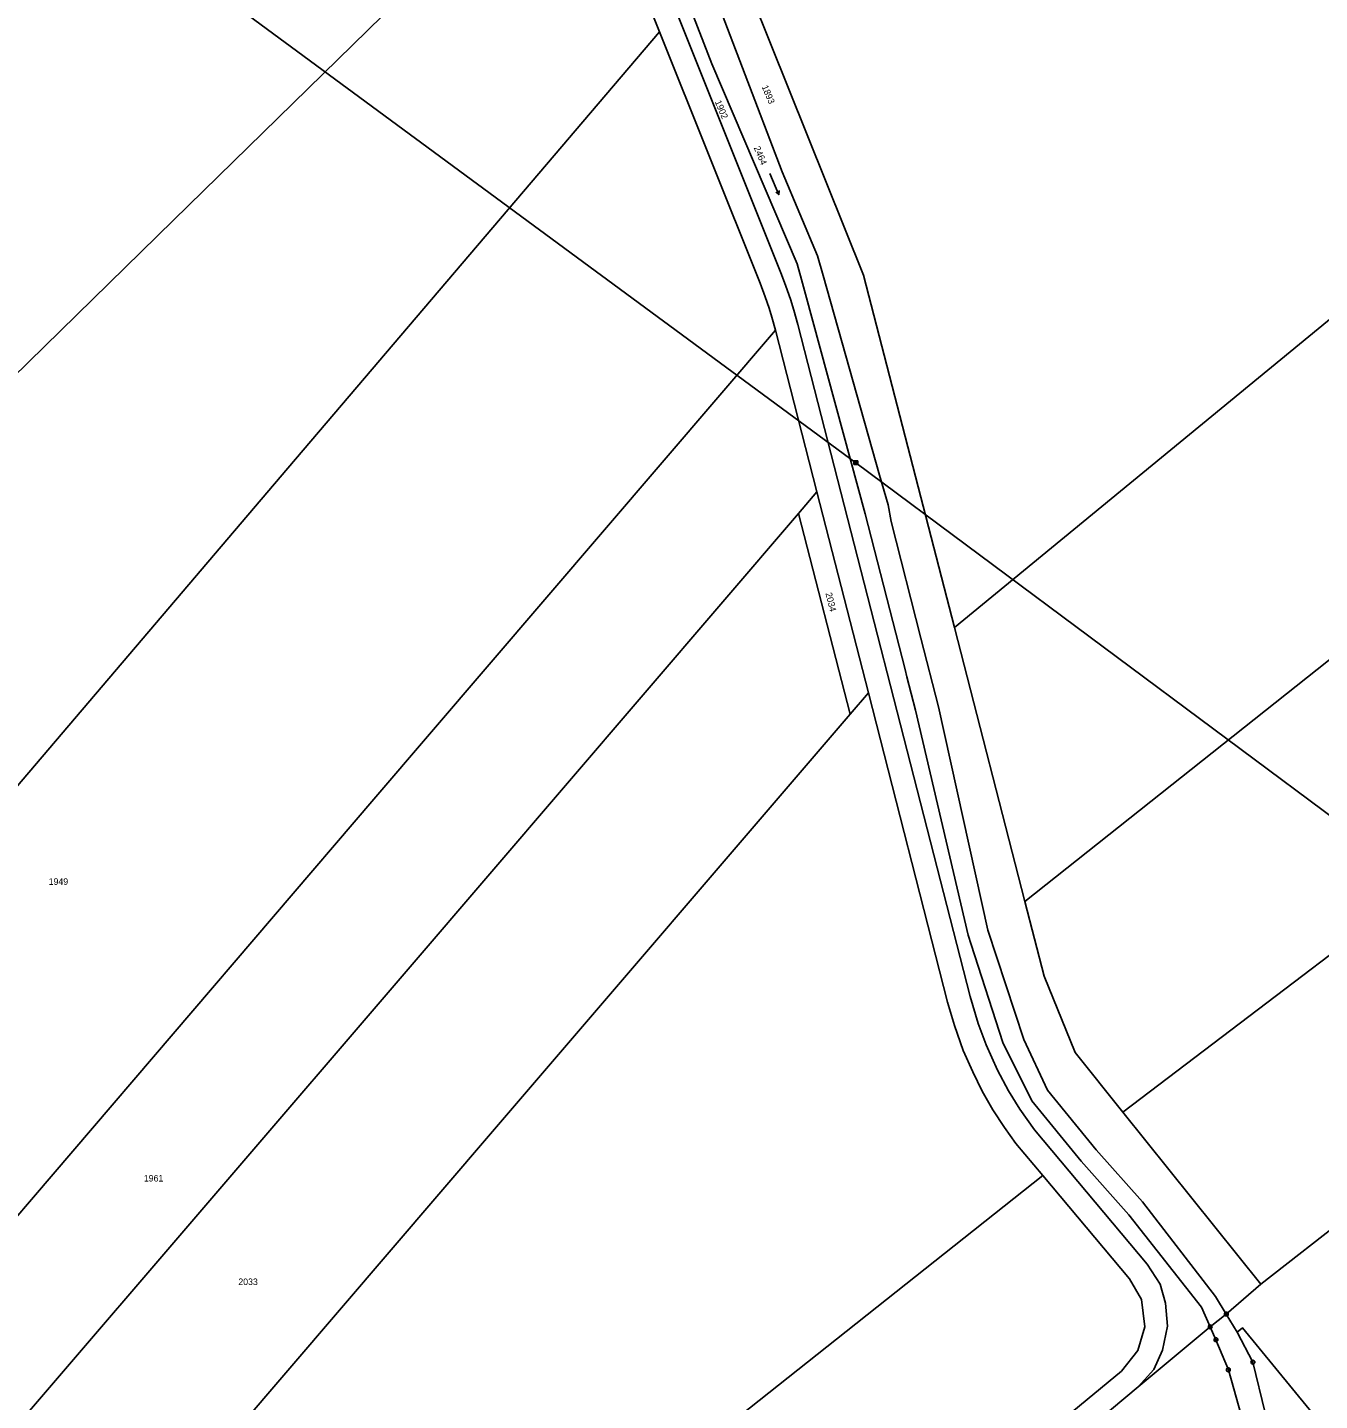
# Model space of a CAD drawing. Extents: x -504988 to -494607, y -1123820 to -1114018.
# Drawn here: x -501568.7 to -501232.9, y -1120604.7 to -1120247.9 of the extents above; entities that cross this region are included whole.
import ezdxf

# ---------------------------------------------------------------- set-up
doc = ezdxf.new("R2010")
doc.units = 0
for name, color, linetype in [('Hranice parcel', 7, 'Continuous'), ('Parcelní čísla', 7, 'Continuous'), ('Poz předměty', 7, 'Continuous'), ('Značky bodu BP', 7, 'Continuous'), ('Značky kultur', 7, 'Continuous')]:
    doc.layers.add(name, color=color, linetype=linetype)

msp = doc.modelspace()

# ---------------------------------------------------------------- linework, layer by layer
at = {"layer": 'Hranice parcel'}
for p, q in [((-501404.45, -1120249.05), (-501425.9, -1120195.48)), ((-501363.52, -1120368.63), (-501374.29, -1120326.57)), ((-501368.29, -1120374.19), (-501363.52, -1120368.63)), ((-501350.15, -1120420.8), (-501363.52, -1120368.63)), ((-501354.92, -1120426.36), (-501368.29, -1120374.19)), ((-501309.46, -1120475.02), (-501327.8, -1120403.85)), ((-501350.15, -1120420.8), (-501354.92, -1120426.36)), ((-501186.29, -1120526.21), (-501248.19, -1120574.48)), ((-501248.19, -1120574.48), (-501283.99, -1120529.75)), ((-501248.19, -1120574.48), (-501257.14, -1120582.25)), ((-501261.34, -1120585.56), (-501257.14, -1120582.25)), ((-501257.14, -1120582.25), (-501254.29, -1120586.94)), ((-501261.34, -1120585.56), (-501280.06, -1120601.16)), ((-501280.06, -1120601.16), (-501364.05, -1120671.17))]:
    msp.add_line(p, q, dxfattribs=at)
for points in [[(-501327.8, -1120403.85), (-501351.4, -1120312.32), (-501404.66, -1120179.5)], [(-501261.34, -1120585.56), (-501263.62, -1120580.47), (-501282.51, -1120556.48), (-501294.84, -1120542.51), (-501307.66, -1120526.86), (-501315.22, -1120511.72), (-501323.4, -1120486.24), (-501324.18, -1120483.81), (-501337.91, -1120425.3), (-501340.13, -1120416.63), (-501340.62, -1120414.73), (-501350.97, -1120374.34), (-501366.51, -1120317.27), (-501367.55, -1120313.46), (-501368.67, -1120309.33), (-501390.83, -1120257.4), (-501417.17, -1120189.27)], [(-501740.45, -1120503.19), (-501635.6, -1120400.62), (-501530.75, -1120298.05), (-501425.9, -1120195.48)], [(-501327.8, -1120403.85), (-501217.73, -1120313.47), (-501107.66, -1120223.08)], [(-501404.12, -1120233.67), (-501372.72, -1120312.15), (-501371.56, -1120315.17), (-501370.4, -1120318.55), (-501369.5, -1120321.42), (-501368.48, -1120325.08), (-501323.74, -1120499.74), (-501321.65, -1120506.76), (-501319.53, -1120512.26), (-501316.61, -1120518.89), (-501313.71, -1120524.28), (-501310.77, -1120529.03), (-501306.99, -1120534.38), (-501277.67, -1120569.26), (-501274.35, -1120574.51), (-501272.91, -1120579.44), (-501272.42, -1120585.43), (-501273.68, -1120591.65), (-501276.01, -1120596.62), (-501280.06, -1120601.16)], [(-501393.18, -1120231.31), (-501372.59, -1120285.43), (-501363.37, -1120307.31), (-501361.94, -1120312.37), (-501347.23, -1120364.25), (-501345.04, -1120371.97), (-501344.25, -1120376.28), (-501336.5, -1120406.6), (-501331.95, -1120424.43), (-501319.09, -1120482.5), (-501309.78, -1120510.94), (-501303.61, -1120524.09), (-501290.93, -1120539.58), (-501278.88, -1120553.13), (-501259.92, -1120577.69), (-501257.14, -1120582.25)], [(-501694.2, -1120589.18), (-501597.62, -1120475.8), (-501501.03, -1120362.43), (-501404.45, -1120249.05)], [(-501374.29, -1120326.57), (-501375.21, -1120323.23), (-501375.93, -1120320.89), (-501376.94, -1120317.94), (-501378.29, -1120314.39), (-501404.45, -1120249.05)], [(-501309.46, -1120475.02), (-501181.95, -1120373.83), (-501054.44, -1120272.63)], [(-501583.01, -1120570.44), (-501478.65, -1120448.5), (-501374.29, -1120326.57)], [(-501671.16, -1120727.67), (-501570.2, -1120609.84), (-501469.25, -1120492.02), (-501368.29, -1120374.19)], [(-501283.99, -1120529.75), (-501183.6, -1120453.57), (-501083.21, -1120377.38)], [(-501304.82, -1120546.26), (-501311.85, -1120537.89), (-501314.81, -1120533.74), (-501317.8, -1120529.14), (-501320.57, -1120524.3), (-501323.05, -1120519.35), (-501325.48, -1120513.73), (-501327.77, -1120507.26), (-501329.55, -1120501.23), (-501350.15, -1120420.8)], [(-501354.92, -1120426.36), (-501447.86, -1120534.83), (-501540.79, -1120643.3), (-501633.73, -1120751.77)], [(-501283.99, -1120529.75), (-501296.38, -1120514.27), (-501304.46, -1120494.41), (-501309.46, -1120475.02)], [(-501560.18, -1120786.67), (-501527.75, -1120804.11), (-501524.45, -1120805.17), (-501521.73, -1120805.12), (-501519.08, -1120804.28), (-501516.34, -1120802.26), (-501462.32, -1120744.93), (-501457.75, -1120740.38), (-501452.9, -1120736.12), (-501368.66, -1120666.62), (-501284.41, -1120597.12), (-501280.12, -1120591.76), (-501278.34, -1120585.57), (-501279.22, -1120578.46), (-501282.26, -1120573.12), (-501304.82, -1120546.26)], [(-501304.82, -1120546.26), (-501429.67, -1120645.23), (-501530.63, -1120737.12), (-501555.87, -1120775.45)], [(-501246.29, -1120653.02), (-501250.02, -1120623.58), (-501253.23, -1120608.78), (-501256.61, -1120596.72), (-501259.83, -1120588.92), (-501261.34, -1120585.56)], [(-501195.89, -1120655.5), (-501252.94, -1120585.81), (-501254.29, -1120586.94)], [(-501254.29, -1120586.94), (-501250.23, -1120594.76), (-501247.04, -1120607.91), (-501244.45, -1120622.7), (-501241.9, -1120650.35), (-501238.49, -1120682.81)]]:
    msp.add_lwpolyline(points, dxfattribs=at)
at = {"layer": 'Poz předměty'}
for p, q in [((-501521.61, -1120237.13), (-501353.43, -1120361.04)), ((-501353.93, -1120360.54), (-501352.93, -1120360.54)), ((-501353.93, -1120361.54), (-501353.93, -1120360.54)), ((-501353.93, -1120360.74), (-501352.93, -1120360.74)), ((-501353.93, -1120360.94), (-501352.93, -1120360.94)), ((-501353.93, -1120361.14), (-501352.93, -1120361.14)), ((-501353.93, -1120361.34), (-501352.93, -1120361.34)), ((-501353.93, -1120361.54), (-501352.93, -1120361.54)), ((-501353.73, -1120361.54), (-501353.73, -1120360.54)), ((-501353.53, -1120361.54), (-501353.53, -1120360.54)), ((-501353.43, -1120361.04), (-501198.35, -1120476.45)), ((-501353.33, -1120361.54), (-501353.33, -1120360.54)), ((-501353.13, -1120361.54), (-501353.13, -1120360.54)), ((-501352.93, -1120361.54), (-501352.93, -1120360.54))]:
    msp.add_line(p, q, dxfattribs=at)
at = {"layer": 'Značky bodu BP'}
for centre, radius in [((-501257.14, -1120582.25), 0.5), ((-501257.14, -1120582.25), 0.0303), ((-501261.34, -1120585.56), 0.5), ((-501261.34, -1120585.56), 0.0303), ((-501259.83, -1120588.92), 0.5), ((-501259.83, -1120588.92), 0.0303), ((-501256.61, -1120596.72), 0.5), ((-501256.61, -1120596.72), 0.0303), ((-501250.23, -1120594.76), 0.5), ((-501250.23, -1120594.76), 0.0303)]:
    msp.add_circle(centre, radius, dxfattribs=at)
at = {"layer": 'Značky kultur'}
for p, q in [((-501375.74, -1120285.89), (-501373.4, -1120291.41)), ((-501373.4, -1120291.41), (-501374.24, -1120290.71)), ((-501373.4, -1120291.41), (-501373.32, -1120290.31))]:
    msp.add_line(p, q, dxfattribs=at)

# ---------------------------------------------------------------- texts
at = {"layer": 'Parcelní čísla'}
for s, rotation, p in [('1893', 293, (-501377.91, -1120263.34)), ('1902', 293, (-501390.09, -1120267.25)), ('2464', 293, (-501379.97, -1120279.19)), ('2034', 284, (-501361.31, -1120394.97))]:
    msp.add_text(s, height=1.7, rotation=rotation, dxfattribs=at).set_placement(p)
for s, p in [('1949', (-501563.15, -1120470.72)), ('1961', (-501538.42, -1120547.81)), ('2033', (-501513.87, -1120574.71))]:
    msp.add_text(s, height=1.7, dxfattribs=at).set_placement(p)

doc.saveas('drawing.dxf')
